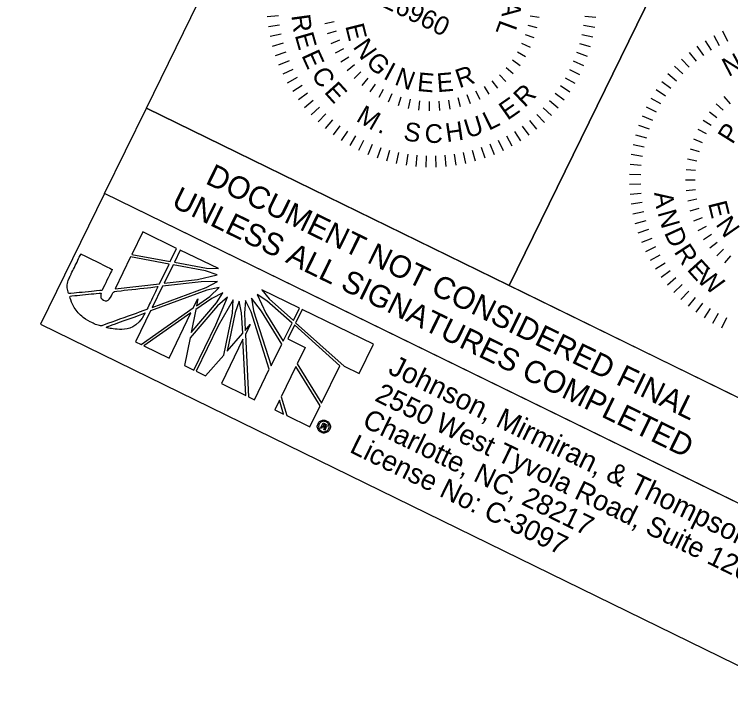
# Model space of a CAD drawing. Extents: x 1518247 to 1523638, y 635234 to 639927.
# Drawn here: x 1521655.6 to 1521833.1, y 637014.1 to 637183 of the extents above; entities that cross this region are included whole.
import ezdxf

# ---------------------------------------------------------------- set-up
doc = ezdxf.new("R2010")
doc.units = 0
for name, color, linetype in [('Default', 7, 'Continuous'), ('DTM TIN Hull White', 7, 'Continuous'), ('Sheet Sticker Exception Certification CELL', 7, 'Continuous'), ('Sheet Typical CELL', 7, 'Continuous'), ('Typical Text Label CELL', 7, 'Continuous')]:
    doc.layers.add(name, color=color, linetype=linetype)

msp = doc.modelspace()

# ---------------------------------------------------------------- linework, layer by layer
at = {"layer": 'Default'}
for p, q in [((1521687.44, 637129.17), (1521684.72, 637123.59)), ((1521695.85, 637125.06), (1521687.44, 637129.17)), ((1521694.27, 637121.81), (1521695.85, 637125.06)), ((1521696.75, 637124.68), (1521695.28, 637121.67)), ((1521706.22, 637120.06), (1521696.75, 637124.68)), ((1521684.41, 637122.95), (1521680.58, 637115.1)), ((1521693.97, 637121.2), (1521684.41, 637122.95)), ((1521684.72, 637123.59), (1521694.27, 637121.81)), ((1521691.59, 637116.33), (1521693.97, 637121.2)), ((1521694.96, 637121.01), (1521692.74, 637116.46)), ((1521702.96, 637119.52), (1521694.96, 637121.01)), ((1521695.28, 637121.67), (1521703.28, 637120.17)), ((1521703.28, 637120.17), (1521706.22, 637120.06)), ((1521701.01, 637117.38), (1521705.87, 637118.51)), ((1521705.87, 637118.51), (1521702.96, 637119.52)), ((1521701.93, 637116.8), (1521692.38, 637115.72)), ((1521692.74, 637116.46), (1521701.01, 637117.38)), ((1521705.93, 637116.86), (1521701.93, 637116.8)), ((1521703.19, 637115.38), (1521705.93, 637116.86)), ((1521680.58, 637115.1), (1521691.59, 637116.33)), ((1521692.38, 637115.72), (1521689.82, 637110.48)), ((1521689.82, 637110.48), (1521703.19, 637115.38)), ((1521706.41, 637115.38), (1521703.33, 637114.75)), ((1521704.07, 637113.18), (1521706.41, 637115.38)), ((1521726.24, 637110.24), (1521716.93, 637114.83)), ((1521716.93, 637114.83), (1521718.75, 637112.57)), ((1521703.33, 637114.75), (1521689.39, 637109.59)), ((1521700.74, 637110.84), (1521704.07, 637113.18)), ((1521707.25, 637114.04), (1521704.54, 637112.71)), ((1521705.75, 637111.56), (1521707.25, 637114.04)), ((1521715.79, 637113.67), (1521717.9, 637109.06)), ((1521718.22, 637112.07), (1521715.79, 637113.67)), ((1521699.47, 637104.22), (1521705.75, 637111.56)), ((1521699.98, 637110.35), (1521701.07, 637112.57)), ((1521704.54, 637112.71), (1521700.59, 637109.93)), ((1521701.07, 637112.57), (1521700.74, 637110.84)), ((1521705.58, 637106.17), (1521708.45, 637112.98)), ((1521708.45, 637112.98), (1521705.99, 637110.85)), ((1521709.84, 637112.31), (1521706.17, 637105.88)), ((1521709.64, 637109.07), (1521709.84, 637112.31)), ((1521711.37, 637112.03), (1521710.34, 637109.2)), ((1521711.95, 637109.09), (1521711.37, 637112.03)), ((1521712.93, 637112.19), (1521712.65, 637109)), ((1521714.33, 637109.38), (1521712.93, 637112.19)), ((1521714.41, 637112.72), (1521714.91, 637109.61)), ((1521716.87, 637109.52), (1521714.41, 637112.72)), ((1521724.46, 637106.57), (1521718.22, 637112.07)), ((1521718.75, 637112.57), (1521724.77, 637107.21)), ((1521689.39, 637109.59), (1521685.66, 637101.95)), ((1521687.05, 637101.27), (1521699.98, 637110.35)), ((1521705.99, 637110.85), (1521699.18, 637102.92)), ((1521700.59, 637109.93), (1521699.47, 637104.22)), ((1521714.91, 637109.61), (1521719.23, 637096)), ((1521721.86, 637101.39), (1521716.87, 637109.52)), ((1521724.77, 637107.21), (1521726.24, 637110.24)), ((1521726.92, 637109.96), (1521725.33, 637106.71)), ((1521744.6, 637101.33), (1521726.92, 637109.96)), ((1521699.39, 637109.14), (1521687.7, 637100.96)), ((1521693.98, 637097.89), (1521699.39, 637109.14)), ((1521707.55, 637098.66), (1521709.64, 637109.07)), ((1521710.34, 637109.2), (1521708.37, 637099.64)), ((1521712.21, 637104.09), (1521711.95, 637109.09)), ((1521712.65, 637109), (1521712.82, 637104.77)), ((1521718.8, 637095.13), (1521714.33, 637109.38)), ((1521717.9, 637109.06), (1521722.23, 637102.14)), ((1521700.1, 637094.95), (1521705.58, 637106.17)), ((1521712.82, 637104.77), (1521714.06, 637106.23)), ((1521714.06, 637106.23), (1521712.86, 637103.77)), ((1521722.23, 637102.14), (1521724.46, 637106.57)), ((1521725.01, 637106.06), (1521723.36, 637102.67)), ((1521725.04, 637106.11), (1521725.01, 637106.06)), ((1521736.26, 637096.03), (1521725.04, 637106.11)), ((1521725.33, 637106.71), (1521725.28, 637106.61)), ((1521725.28, 637106.61), (1521737.31, 637095.92)), ((1521706.17, 637105.88), (1521700.7, 637094.66)), ((1521699.18, 637102.92), (1521697.8, 637096.08)), ((1521712.27, 637102.56), (1521706.94, 637091.62)), ((1521708.37, 637099.64), (1521712.21, 637104.09)), ((1521712.96, 637088.68), (1521712.27, 637102.56)), ((1521712.86, 637103.77), (1521713.63, 637088.3)), ((1521723.36, 637102.67), (1521727.68, 637100.56)), ((1521685.66, 637101.95), (1521687.05, 637101.27)), ((1521687.7, 637100.96), (1521693.98, 637097.89)), ((1521719.23, 637096), (1521721.86, 637101.39)), ((1521741.07, 637094.08), (1521744.6, 637101.33)), ((1521727.68, 637100.56), (1521725.71, 637096.52)), ((1521703.03, 637093.53), (1521707.55, 637098.66)), ((1521697.8, 637096.08), (1521700.1, 637094.95)), ((1521725.37, 637095.83), (1521721.7, 637088.3)), ((1521731.41, 637086.09), (1521725.37, 637095.83)), ((1521725.71, 637096.52), (1521731.73, 637086.74)), ((1521731.73, 637086.74), (1521736.26, 637096.03)), ((1521737.31, 637095.92), (1521741.07, 637094.08)), ((1521700.7, 637094.66), (1521703.03, 637093.53)), ((1521715.12, 637087.58), (1521718.8, 637095.13)), ((1521706.94, 637091.62), (1521712.96, 637088.68)), ((1521713.63, 637088.3), (1521715.12, 637087.58)), ((1521721.7, 637088.3), (1521723.16, 637083.66)), ((1521721.3, 637087.49), (1521720.15, 637085.13)), ((1521722.33, 637084.06), (1521721.3, 637087.49)), ((1521720.15, 637085.13), (1521722.33, 637084.06)), ((1521728.86, 637080.87), (1521731.41, 637086.09)), ((1521723.16, 637083.66), (1521728.86, 637080.87)), ((1521731.47, 637080.58), (1521732.1, 637081.87)), ((1521732.1, 637081.87), (1521732.62, 637081.61)), ((1521732.27, 637081.48), (1521732.12, 637081.18)), ((1521732.12, 637081.18), (1521732.35, 637081.06)), ((1521732.35, 637081.06), (1521732.24, 637080.83)), ((1521732.24, 637080.83), (1521732.35, 637081.06)), ((1521732.5, 637081.37), (1521732.27, 637081.48)), ((1521732.35, 637081.06), (1521732.36, 637081.06)), ((1521732.62, 637081.61), (1521732.5, 637081.37)), ((1521732.5, 637081.37), (1521732.62, 637081.61)), ((1521732.54, 637081.35), (1521732.5, 637081.37)), ((1521732.62, 637081.61), (1521732.7, 637081.57)), ((1521732.99, 637082.37), (1521732.86, 637082.11)), ((1521732.86, 637082.11), (1521732.99, 637082.37)), ((1521731.76, 637080.44), (1521731.47, 637080.58)), ((1521731.75, 637079.83), (1521731.61, 637079.54)), ((1521731.61, 637079.54), (1521731.75, 637079.83)), ((1521731.62, 637079.54), (1521731.61, 637079.54)), ((1521731.75, 637079.83), (1521731.76, 637079.82)), ((1521732.01, 637080.94), (1521731.76, 637080.44)), ((1521732.24, 637080.83), (1521732.01, 637080.94)), ((1521732.25, 637080.83), (1521732.24, 637080.83))]:
    msp.add_line(p, q, dxfattribs=at)
msp.add_lwpolyline([(1521662.15, 637106.28), (1521841.85, 637018.4), (1521857.71, 637050.82), (1521678.01, 637138.71)], close=True, dxfattribs=at)
for points in [[(1521684.72, 637123.59), (1521694.27, 637121.81), (1521695.85, 637125.06), (1521687.44, 637129.17), (1521684.72, 637123.59)], [(1521703.28, 637120.17), (1521706.22, 637120.06), (1521696.75, 637124.68), (1521695.28, 637121.67), (1521703.28, 637120.17)], [(1521680.58, 637115.1), (1521691.59, 637116.33), (1521693.97, 637121.2), (1521684.41, 637122.95), (1521680.58, 637115.1)], [(1521694.96, 637121.01), (1521692.74, 637116.46), (1521701.01, 637117.38), (1521705.87, 637118.51), (1521702.96, 637119.52), (1521694.96, 637121.01)], [(1521692.38, 637115.72), (1521689.82, 637110.48), (1521703.19, 637115.38), (1521705.93, 637116.86), (1521701.93, 637116.8), (1521692.38, 637115.72)], [(1521706.41, 637115.38), (1521703.33, 637114.75), (1521689.39, 637109.59), (1521685.66, 637101.95), (1521687.05, 637101.27), (1521699.98, 637110.35), (1521701.07, 637112.57), (1521700.74, 637110.84), (1521704.07, 637113.18), (1521706.41, 637115.38)], [(1521718.75, 637112.57), (1521724.77, 637107.21), (1521726.24, 637110.24), (1521716.93, 637114.83), (1521718.75, 637112.57)], [(1521707.25, 637114.04), (1521704.54, 637112.71), (1521700.59, 637109.93), (1521699.47, 637104.22), (1521705.75, 637111.56), (1521707.25, 637114.04)], [(1521715.79, 637113.67), (1521717.9, 637109.06), (1521722.23, 637102.14), (1521724.46, 637106.57), (1521718.22, 637112.07), (1521715.79, 637113.67)], [(1521705.99, 637110.85), (1521699.18, 637102.92), (1521697.8, 637096.08), (1521700.1, 637094.95), (1521705.58, 637106.17), (1521708.45, 637112.98), (1521705.99, 637110.85)], [(1521709.84, 637112.31), (1521706.17, 637105.88), (1521700.7, 637094.66), (1521703.03, 637093.53), (1521707.55, 637098.66), (1521709.64, 637109.07), (1521709.84, 637112.31)], [(1521711.37, 637112.03), (1521710.34, 637109.2), (1521708.37, 637099.64), (1521712.21, 637104.09), (1521711.95, 637109.09), (1521711.37, 637112.03)], [(1521712.93, 637112.19), (1521712.65, 637109), (1521712.82, 637104.77), (1521714.06, 637106.23), (1521712.86, 637103.77), (1521713.63, 637088.3), (1521715.12, 637087.58), (1521718.8, 637095.13), (1521714.33, 637109.38), (1521712.93, 637112.19)], [(1521714.41, 637112.72), (1521714.91, 637109.61), (1521719.23, 637096), (1521721.86, 637101.39), (1521716.87, 637109.52), (1521714.41, 637112.72)], [(1521744.6, 637101.33), (1521726.92, 637109.96), (1521725.33, 637106.71), (1521725.28, 637106.61), (1521737.31, 637095.92), (1521741.07, 637094.08), (1521744.6, 637101.33)], [(1521687.7, 637100.96), (1521693.98, 637097.89), (1521699.39, 637109.14), (1521687.7, 637100.96)], [(1521725.04, 637106.11), (1521725.01, 637106.06), (1521723.36, 637102.67), (1521727.68, 637100.56), (1521725.71, 637096.52), (1521731.73, 637086.74), (1521736.26, 637096.03), (1521725.04, 637106.11)], [(1521706.94, 637091.62), (1521712.96, 637088.68), (1521712.27, 637102.56), (1521706.94, 637091.62)], [(1521725.37, 637095.83), (1521721.7, 637088.3), (1521723.16, 637083.66), (1521728.86, 637080.87), (1521731.41, 637086.09), (1521725.37, 637095.83), (1521725.37, 637095.83)], [(1521720.15, 637085.13), (1521720.15, 637085.13), (1521722.33, 637084.06), (1521721.3, 637087.49), (1521720.15, 637085.13)], [(1521732.7, 637080.36), (1521732.67, 637080.29), (1521732.66, 637080.24), (1521732.63, 637080.19), (1521732.6, 637080.03), (1521732.33, 637080.16)]]:
    msp.add_lwpolyline(points, dxfattribs=at)
for points, degree in [([(1521679.92, 637119.89), (1521679.92, 637119.89), (1521672.14, 637123.69), (1521672.14, 637123.69), (1521672.14, 637123.69), (1521669.76, 637118.82), (1521669.76, 637118.82), (1521669.76, 637118.82), (1521669.51, 637118.31), (1521669.51, 637118.31), (1521668.76, 637116.78), (1521668.67, 637115.33), (1521669.07, 637113.88), (1521669.07, 637113.88), (1521677.36, 637114.64), (1521677.41, 637114.74), (1521677.41, 637114.74), (1521679.92, 637119.89), (1521679.92, 637119.89)], 3), ([(1521677.71, 637112.29), (1521677.21, 637112.54), (1521676.92, 637113.02), (1521677.19, 637114.04), (1521677.19, 637114.04), (1521669.33, 637113.25), (1521669.33, 637113.25), (1521670.23, 637110.39), (1521672.64, 637107.77), (1521675.15, 637106.55), (1521675.8, 637106.23), (1521676.33, 637106.04), (1521677.09, 637105.84), (1521677.09, 637105.84), (1521688.49, 637109.97), (1521688.49, 637109.97), (1521688.49, 637109.97), (1521691.25, 637115.64), (1521691.25, 637115.64), (1521691.25, 637115.64), (1521680.23, 637114.4), (1521680.23, 637114.4), (1521679.2, 637112.27), (1521678.41, 637111.95), (1521677.71, 637112.29)], 3), ([(1521677.71, 637112.29), (1521677.21, 637112.54), (1521676.92, 637113.02), (1521677.19, 637114.04), (1521677.19, 637114.04), (1521669.33, 637113.25), (1521669.33, 637113.25), (1521670.23, 637110.39), (1521672.64, 637107.77), (1521675.15, 637106.55), (1521675.8, 637106.23), (1521676.33, 637106.04), (1521677.09, 637105.84), (1521677.09, 637105.84), (1521688.49, 637109.97), (1521688.49, 637109.97), (1521688.49, 637109.97), (1521691.25, 637115.64), (1521691.25, 637115.64), (1521691.25, 637115.64), (1521680.23, 637114.4), (1521680.23, 637114.4), (1521679.2, 637112.27), (1521678.41, 637111.95), (1521677.71, 637112.29)], 3), ([(1521688.06, 637109.08), (1521688.06, 637109.08), (1521678.21, 637105.52), (1521678.21, 637105.52), (1521681.8, 637104.75), (1521686.03, 637105.31), (1521688.06, 637109.08)], 3), ([(1521731.61, 637079.54), (1521731.23, 637079.73), (1521730.96, 637080.04), (1521730.81, 637080.46), (1521730.66, 637080.86), (1521730.69, 637081.27), (1521730.88, 637081.67), (1521731.07, 637082.06), (1521731.38, 637082.34), (1521731.79, 637082.46), (1521732.2, 637082.59), (1521732.59, 637082.57), (1521732.99, 637082.37)], 3), ([(1521732.86, 637082.11), (1521732.55, 637082.26), (1521732.22, 637082.29), (1521731.9, 637082.18), (1521731.57, 637082.07), (1521731.32, 637081.85), (1521731.16, 637081.53), (1521731.01, 637081.21), (1521730.99, 637080.88), (1521731.1, 637080.55), (1521731.22, 637080.22), (1521731.43, 637079.98), (1521731.75, 637079.83)], 3), ([(1521731.76, 637079.82), (1521732.08, 637079.67), (1521732.4, 637079.64), (1521732.73, 637079.75), (1521733.06, 637079.87), (1521733.31, 637080.09), (1521733.47, 637080.41), (1521733.62, 637080.72), (1521733.64, 637081.06), (1521733.53, 637081.39), (1521733.41, 637081.71), (1521733.19, 637081.95), (1521732.86, 637082.11)], 3), ([(1521732.36, 637081.06), (1521732.55, 637080.97), (1521732.67, 637080.98), (1521732.73, 637081.09), (1521732.77, 637081.18), (1521732.71, 637081.27), (1521732.54, 637081.35)], 3), ([(1521732.7, 637081.57), (1521733.03, 637081.41), (1521733.13, 637081.21), (1521733.01, 637080.95), (1521732.95, 637080.83), (1521732.86, 637080.76), (1521732.72, 637080.74)], 3), ([(1521732.99, 637082.37), (1521733.39, 637082.18), (1521733.66, 637081.87), (1521733.81, 637081.47), (1521733.96, 637081.07), (1521733.94, 637080.67), (1521733.75, 637080.27)], 3), ([(1521733.75, 637080.27), (1521733.55, 637079.87), (1521733.25, 637079.6), (1521732.84, 637079.45), (1521732.43, 637079.32), (1521732.02, 637079.34), (1521731.62, 637079.54)], 3), ([(1521732.45, 637080.67), (1521732.43, 637080.71), (1521732.37, 637080.77), (1521732.25, 637080.83)], 2), ([(1521732.33, 637080.16), (1521732.33, 637080.25), (1521732.34, 637080.33), (1521732.39, 637080.42), (1521732.45, 637080.54), (1521732.47, 637080.62), (1521732.45, 637080.67)], 3), ([(1521732.72, 637080.74), (1521732.78, 637080.66), (1521732.77, 637080.53), (1521732.7, 637080.36)], 2)]:
    msp.add_open_spline(points, degree=degree, dxfattribs=at)
at = {"layer": 'DTM TIN Hull White'}
for p, q in [((1521718.28, 637182.49), (1521721.06, 637182.73)), ((1521785.67, 637182.27), (1521783.37, 637182.6)), ((1521799.7, 637182.27), (1521796.92, 637182.53)), ((1521718.57, 637180.03), (1521721.33, 637180.45)), ((1521732.58, 637180.81), (1521734.86, 637181.26)), ((1521733.21, 637178.29), (1521735.43, 637178.96)), ((1521785.18, 637179.72), (1521782.92, 637180.27)), ((1521799.4, 637179.82), (1521796.64, 637180.25)), ((1521831.06, 637178.93), (1521832.27, 637176.42)), ((1521719.01, 637177.61), (1521721.74, 637178.18)), ((1521784.44, 637177.22), (1521782.25, 637177.99)), ((1521798.94, 637177.39), (1521796.22, 637177.98)), ((1521828.87, 637177.79), (1521830.23, 637175.36)), ((1521719.6, 637175.2), (1521722.28, 637175.95)), ((1521734.08, 637175.84), (1521736.23, 637176.72)), ((1521783.47, 637174.81), (1521781.36, 637175.78)), ((1521798.35, 637174.99), (1521795.67, 637175.75)), ((1521824.72, 637175.12), (1521826.36, 637172.87)), ((1521826.75, 637176.52), (1521828.26, 637174.17)), ((1521720.33, 637172.85), (1521722.96, 637173.75)), ((1521735.19, 637173.48), (1521737.24, 637174.56)), ((1521782.27, 637172.5), (1521780.26, 637173.67)), ((1521797.6, 637172.64), (1521794.97, 637173.56)), ((1521822.77, 637173.6), (1521824.55, 637171.46)), ((1521721.19, 637170.54), (1521723.77, 637171.59)), ((1521736.51, 637171.24), (1521738.46, 637172.52)), ((1521779.01, 637171.74), (1521780.9, 637170.39)), ((1521820.92, 637171.97), (1521822.82, 637169.93)), ((1521738.05, 637169.14), (1521739.86, 637170.6)), ((1521779.23, 637168.28), (1521777.48, 637169.81)), ((1521796.72, 637170.33), (1521794.15, 637171.41)), ((1521819.17, 637170.23), (1521821.19, 637168.31)), ((1521722.2, 637168.28), (1521724.71, 637169.49)), ((1521739.79, 637167.19), (1521741.45, 637168.82)), ((1521777.41, 637166.41), (1521775.83, 637168.1)), ((1521795.7, 637168.08), (1521793.2, 637169.31)), ((1521817.52, 637168.38), (1521819.66, 637166.6)), ((1521723.34, 637166.09), (1521725.77, 637167.45)), ((1521743.18, 637167.22), (1521741.68, 637165.44)), ((1521775.43, 637164.73), (1521774.02, 637166.57)), ((1521794.55, 637165.9), (1521792.13, 637167.27)), ((1521816, 637166.45), (1521818.23, 637164.79)), ((1521724.61, 637163.98), (1521726.96, 637165.48)), ((1521743.77, 637163.85), (1521745.08, 637165.77)), ((1521745.99, 637162.49), (1521747.11, 637164.52)), ((1521773.29, 637163.24), (1521772.06, 637165.21)), ((1521793.26, 637163.79), (1521790.93, 637165.31)), ((1521726.01, 637161.94), (1521728.26, 637163.59)), ((1521748.32, 637161.34), (1521749.25, 637163.47)), ((1521768.64, 637160.92), (1521767.81, 637163.09)), ((1521771.02, 637161.96), (1521769.98, 637164.04)), ((1521791.86, 637161.76), (1521789.62, 637163.42)), ((1521814.59, 637164.42), (1521816.92, 637162.9)), ((1521727.53, 637159.99), (1521729.67, 637161.77)), ((1521750.76, 637160.43), (1521751.47, 637162.64)), ((1521753.28, 637159.75), (1521753.77, 637162.02)), ((1521755.84, 637159.32), (1521756.11, 637161.63)), ((1521758.44, 637159.14), (1521758.49, 637161.47)), ((1521761.04, 637159.21), (1521760.87, 637161.53)), ((1521763.63, 637159.54), (1521763.23, 637161.82)), ((1521766.17, 637160.11), (1521765.55, 637162.35)), ((1521790.33, 637159.83), (1521788.2, 637161.61)), ((1521813.31, 637162.31), (1521815.73, 637160.93)), ((1521831.41, 637162.66), (1521832.92, 637160.89)), ((1521729.16, 637158.14), (1521731.2, 637160.04)), ((1521788.69, 637157.98), (1521786.66, 637159.89)), ((1521812.15, 637160.12), (1521814.65, 637158.9)), ((1521829.51, 637160.88), (1521831.18, 637159.27)), ((1521730.9, 637156.39), (1521732.82, 637158.42)), ((1521786.94, 637156.24), (1521785.03, 637158.27)), ((1521811.13, 637157.87), (1521813.7, 637156.8)), ((1521827.79, 637158.93), (1521829.61, 637157.48)), ((1521732.75, 637154.74), (1521734.53, 637156.88)), ((1521785.08, 637154.61), (1521783.31, 637156.75)), ((1521826.27, 637156.82), (1521828.22, 637155.56)), ((1521734.69, 637153.22), (1521736.34, 637155.46)), ((1521736.72, 637151.81), (1521738.23, 637154.15)), ((1521781.1, 637151.69), (1521779.6, 637154.04)), ((1521783.14, 637153.09), (1521781.49, 637155.34)), ((1521810.25, 637155.57), (1521812.88, 637154.65)), ((1521824.96, 637154.57), (1521827.01, 637153.5)), ((1521738.82, 637150.53), (1521740.2, 637152.95)), ((1521778.98, 637150.42), (1521777.62, 637152.85)), ((1521809.51, 637153.21), (1521812.19, 637152.46)), ((1521823.87, 637152.21), (1521826.02, 637151.34)), ((1521741.01, 637149.37), (1521742.23, 637151.88)), ((1521743.26, 637148.36), (1521744.33, 637150.92)), ((1521774.54, 637148.27), (1521773.48, 637150.85)), ((1521776.8, 637149.28), (1521775.58, 637151.79)), ((1521808.91, 637150.82), (1521811.63, 637150.22)), ((1521745.56, 637147.47), (1521746.48, 637150.1)), ((1521747.92, 637146.73), (1521748.67, 637149.41)), ((1521750.31, 637146.13), (1521750.91, 637148.86)), ((1521767.47, 637146.09), (1521766.89, 637148.81)), ((1521769.87, 637146.67), (1521769.13, 637149.36)), ((1521772.23, 637147.4), (1521771.33, 637150.04)), ((1521823.02, 637149.75), (1521825.24, 637149.09)), ((1521752.74, 637145.68), (1521753.17, 637148.44)), ((1521755.19, 637145.38), (1521755.45, 637148.15)), ((1521757.66, 637145.23), (1521757.75, 637148.01)), ((1521760.12, 637145.22), (1521760.05, 637148)), ((1521762.59, 637145.36), (1521762.34, 637148.13)), ((1521765.04, 637145.65), (1521764.63, 637148.4)), ((1521808.46, 637148.39), (1521811.22, 637147.96)), ((1521822.4, 637147.22), (1521824.68, 637146.78)), ((1521808.16, 637145.94), (1521810.93, 637145.68)), ((1521808, 637143.48), (1521810.79, 637143.38)), ((1521822.03, 637144.64), (1521824.34, 637144.42)), ((1521821.92, 637142.04), (1521824.24, 637142.05)), ((1521807.99, 637141.01), (1521810.78, 637141.08)), ((1521822.05, 637139.44), (1521824.36, 637139.67)), ((1521808.14, 637138.54), (1521810.91, 637138.79)), ((1521808.43, 637136.09), (1521811.18, 637136.5)), ((1521822.43, 637136.87), (1521824.71, 637137.32)), ((1521823.07, 637134.34), (1521825.29, 637135.01)), ((1521808.87, 637133.66), (1521811.59, 637134.24)), ((1521823.94, 637131.89), (1521826.09, 637132.77)), ((1521809.45, 637131.26), (1521812.14, 637132)), ((1521810.18, 637128.9), (1521812.82, 637129.8)), ((1521825.04, 637129.53), (1521827.09, 637130.62)), ((1521811.05, 637126.59), (1521813.62, 637127.65)), ((1521826.37, 637127.29), (1521828.31, 637128.57)), ((1521812.06, 637124.33), (1521814.56, 637125.55)), ((1521827.91, 637125.19), (1521829.71, 637126.65)), ((1521829.64, 637123.25), (1521831.3, 637124.88)), ((1521813.2, 637122.15), (1521815.63, 637123.51)), ((1521833.03, 637123.27), (1521831.54, 637121.49)), ((1521814.47, 637120.03), (1521816.81, 637121.53)), ((1521815.87, 637117.99), (1521818.12, 637119.64)), ((1521817.39, 637116.05), (1521819.53, 637117.83)), ((1521819.02, 637114.19), (1521821.05, 637116.1)), ((1521820.75, 637112.44), (1521822.67, 637114.47)), ((1521822.6, 637110.8), (1521824.39, 637112.94)), ((1521824.54, 637109.27), (1521826.2, 637111.51)), ((1521826.57, 637107.87), (1521828.09, 637110.2)), ((1521828.68, 637106.58), (1521830.05, 637109.01)), ((1521830.86, 637105.43), (1521832.09, 637107.93))]:
    msp.add_line(p, q, dxfattribs=at)
at = {"layer": 'Sheet Sticker Exception Certification CELL'}
for p, q in [((1521678.01, 637138.71), (1521688.34, 637159.82)), ((1521688.34, 637159.82), (1521868.03, 637071.93)), ((1521857.71, 637050.82), (1521678.01, 637138.71))]:
    msp.add_line(p, q, dxfattribs=at)
at = {"layer": 'Sheet Typical CELL'}
msp.add_line((1521827.64, 637216.92), (1521778.24, 637115.91), dxfattribs=at)
for points in [[(1521737.76, 637260.88), (1521827.64, 637216.92), (1521778.21, 637115.86), (1521688.34, 637159.82)], [(1521827.64, 637216.92), (1521917.47, 637172.99), (1521868.05, 637071.93), (1521778.21, 637115.86)]]:
    msp.add_lwpolyline(points, close=True, dxfattribs=at)

# ---------------------------------------------------------------- texts
at = {"layer": 'Default'}
for s, height, p in [('Johnson, Mirmiran, & Thompson Inc.', 5.1112, (1521747.95, 637094.21)), ('2550 West Tyvola Road, Suite 120,', 4.9652, (1521744.66, 637087.47)), ('Charlotte, NC, 28217', 4.9652, (1521741.54, 637081.1)), ('License No: C-3097', 4.9652, (1521738.42, 637074.73))]:
    msp.add_text(s, height=height, rotation=333.9377, dxfattribs=at).set_placement(p)
at = {"layer": 'DTM TIN Hull White'}
for s, rotation, p in [('26960', 333.8847, (1521746.47, 637185.04)), ('A', 265.0516, (1521776.67, 637186.67)), ('R', 277.8197, (1521724.25, 637182.75)), ('E', 283.9548, (1521737.58, 637180.17)), ('L', 249.7554, (1521775.99, 637181.89)), ('E', 285.8915, (1521725.07, 637177.88)), ('N', 304.8099, (1521739.38, 637174.98)), ('E', 294.5343, (1521726.69, 637172.88)), ('N', 27.5614, (1521832.53, 637167.5)), ('G', 313.5761, (1521742.5, 637171.02)), ('C', 303.2069, (1521729.04, 637168.17)), ('I', 331.6709, (1521746.81, 637167.26)), ('N', 339.3006, (1521749.57, 637165.73)), ('R', 18.4496, (1521765.84, 637164.72)), ('E', 354.6926, (1521755.3, 637164.08)), ('E', 4.6785, (1521760.44, 637163.76)), ('E', 312.1794, (1521732.21, 637163.71)), ('R', 43.5571, (1521782, 637159.82)), ('E', 34.8844, (1521777.79, 637156.67)), ('M', 329.9747, (1521740.06, 637156.74)), ('U', 17.2091, (1521767.92, 637152.33)), ('L', 26.0918, (1521773.16, 637154.18)), ('S', 350.5013, (1521751.84, 637151.92)), ('C', 359.5039, (1521757.27, 637151.22)), ('H', 8.3265, (1521762.75, 637151.38)), ('P', 58.0141, (1521833.52, 637150.67)), ('.', 337.717, (1521745.44, 637153.95)), ('A', 277.8197, (1521814.1, 637138.87)), ('E', 283.9548, (1521827.44, 637136.22)), ('N', 285.8915, (1521814.92, 637133.96)), ('N', 304.8099, (1521829.23, 637131.03)), ('D', 294.5343, (1521816.53, 637128.95)), ('R', 303.2069, (1521818.89, 637124.23)), ('E', 312.1794, (1521822.06, 637119.76)), ('W', 321.0521, (1521824.39, 637117.06))]:
    msp.add_text(s, height=4.64, rotation=rotation, dxfattribs=at).set_placement(p)
at = {"layer": 'Sheet Sticker Exception Certification CELL'}
for s, p in [('DOCUMENT NOT CONSIDERED FINAL', (1521702.72, 637141.27)), ('UNLESS ALL SIGNATURES COMPLETED', (1521694.3, 637135.59))]:
    msp.add_text(s, height=5.5, rotation=333.9377, dxfattribs=at).set_placement(p)
at = {"layer": 'Typical Text Label CELL'}
msp.add_text('USE TYPICAL SECTION NO. 4', height=11.8983, rotation=333.8962, dxfattribs=at).set_placement((1521475.15, 637010.97))

doc.saveas('drawing.dxf')
